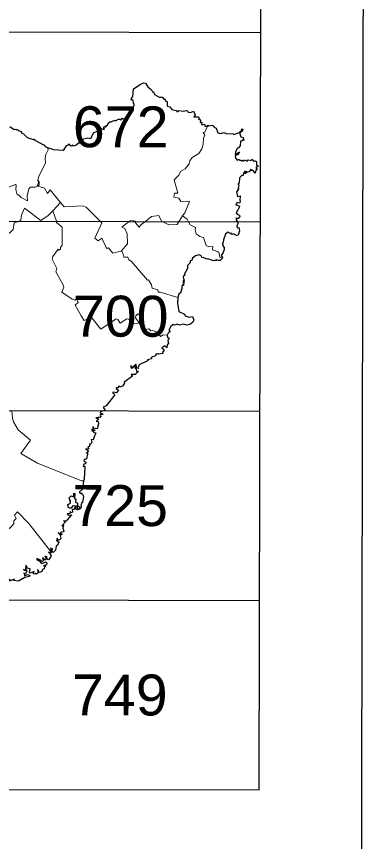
# Model space of a CAD drawing. Extents: x 483840 to 488445, y 4386047 to 4389027.
# Drawn here: x 488278.3 to 488445.3, y 4387758.2 to 4388151.7 of the extents above; entities that cross this region are included whole.
import ezdxf
from ezdxf.enums import TextEntityAlignment as Align

# ---------------------------------------------------------------- set-up
doc = ezdxf.new("R2010")
doc.units = 0
doc.header["$LTSCALE"] = 4
doc.header["$PDMODE"] = 32
doc.header["$PDSIZE"] = 2
doc.linetypes.add('DOTTED', pattern=[1.5, 0.3, -1.2])
for name, color, linetype, lineweight in [('1', 7, 'Continuous', 13), ('2', 7, 'DOTTED', 13), ('3', 7, 'Continuous', 25)]:
    doc.layers.add(name, color=color, linetype=linetype, lineweight=lineweight)

msp = doc.modelspace()

# ---------------------------------------------------------------- linework, layer by layer
at = {"layer": '1', "lineweight": 25}
for p, q in [((488394.11, 4387782.86), (488394.98, 4388234.5)), ((487979.13, 4388144.96), (488394.81, 4388144.16)), ((487840.39, 4388054.9), (488394.63, 4388053.84)), ((487840.22, 4387964.58), (488394.46, 4387963.51)), ((487840.04, 4387874.26), (488394.28, 4387873.19)), ((488116.99, 4387783.39), (488394.11, 4387782.86))]:
    msp.add_line(p, q, dxfattribs=at)
msp.add_lwpolyline([(483845.33, 4389027.42), (488445.32, 4389018.55), (488439.58, 4386047.03), (483839.59, 4386055.9), (483845.33, 4389027.2)], dxfattribs=at)
at = {"layer": '3'}
for p, q in [((488368.22, 4388099.37), (488368.93, 4388099.37)), ((488368.93, 4388099.37), (488369.72, 4388099.83)), ((488369.72, 4388099.83), (488369.49, 4388099.36))]:
    msp.add_line(p, q, dxfattribs=at)
at = {"layer": '3', "lineweight": 13}
msp.add_line((488357.52, 4388056.66), (488355.91, 4388054.17), dxfattribs=at)
at = {"layer": '3'}
for points in [[(488334.17, 4388110.24), (488333.96, 4388111.87), (488333.27, 4388112.11), (488333.16, 4388111.75), (488332.83, 4388112.48), (488333.21, 4388112.45), (488333.49, 4388113.42), (488333.9, 4388113.35), (488334.09, 4388117.22), (488337.38, 4388119.26)], [(488337.38, 4388119.26), (488338.99, 4388120.12), (488339.91, 4388120), (488341.05, 4388118.24), (488342.77, 4388116.73), (488343.16, 4388115.81), (488343.76, 4388115.76), (488344.23, 4388114.53), (488346.39, 4388113.19), (488348.04, 4388113.18), (488348.72, 4388112.21), (488349.26, 4388112.24), (488349.37, 4388111.38)], [(488325.28, 4388102.08), (488325.57, 4388101.94), (488326.98, 4388102.81), (488327.72, 4388102.7), (488328.05, 4388102.2), (488328.67, 4388103.25), (488329.29, 4388102.91), (488330.14, 4388103.11), (488330.76, 4388104.02), (488331.77, 4388104.33), (488332.44, 4388105.15), (488332.18, 4388106.83), (488333.65, 4388107.61), (488334.43, 4388109.33), (488334.53, 4388109.96), (488334.17, 4388110.24)], [(488349.37, 4388111.38), (488349.98, 4388111.38), (488350.26, 4388110.68), (488350.21, 4388108.88), (488351.45, 4388108.56), (488352.51, 4388107.39), (488354.53, 4388106.84), (488354.93, 4388106.32), (488355.74, 4388106.83), (488357.89, 4388106.49), (488359.49, 4388106.94), (488359.97, 4388106.8), (488360.19, 4388106.09), (488361.37, 4388105.94)], [(488361.37, 4388105.94), (488362.74, 4388106.5), (488363.5, 4388104.75), (488362.96, 4388103.81), (488364.94, 4388103.94), (488365.43, 4388103.27), (488365.17, 4388102.66), (488365.64, 4388102.73), (488366.13, 4388102.15), (488365.9, 4388101.17), (488366.69, 4388101.31), (488366.64, 4388100.21), (488366.95, 4388100.08), (488368.03, 4388100.34), (488368.22, 4388099.37)], [(488325.28, 4388102.08), (488323.89, 4388101.66), (488323.73, 4388101.27), (488322.84, 4388101.34), (488321.92, 4388100.57), (488321.36, 4388099.46), (488320.88, 4388099.67), (488320.89, 4388099.26)], [(488275.21, 4388099.24), (488277.18, 4388097.87), (488278.09, 4388098), (488278.38, 4388097.62), (488278.93, 4388097.9), (488279.2, 4388097.28), (488280.55, 4388096.91), (488280.95, 4388096.08), (488281.69, 4388095.83), (488283.39, 4388094.07), (488286.31, 4388093.05), (488286.88, 4388092.92), (488286.57, 4388093.23), (488286.84, 4388093.25), (488287.38, 4388092.63)], [(488320.89, 4388099.26), (488320.73, 4388098.77), (488320.3, 4388099.08), (488319.72, 4388098.76), (488320.17, 4388098.05), (488319.93, 4388097.74), (488318.83, 4388098.07), (488318, 4388097.25), (488317.09, 4388097.61), (488316.91, 4388097.1), (488314.94, 4388096.07), (488313.62, 4388093.35), (488312.4, 4388093.72)], [(488369.72, 4388099.83), (488370.03, 4388099.55), (488371.72, 4388099.93), (488372.47, 4388099.38)], [(488372.47, 4388099.38), (488372.59, 4388098.93), (488373.63, 4388098.54), (488374.45, 4388096.26), (488375.72, 4388095.84), (488377.44, 4388096.45), (488378.37, 4388095.93), (488381.75, 4388095.8), (488382.1, 4388095.37), (488384.52, 4388096.46), (488385.62, 4388097.28), (488385.88, 4388098.12), (488386.55, 4388097.81), (488385.99, 4388097.36), (488386.1, 4388097.07)], [(488312.4, 4388093.72), (488309.73, 4388093.11), (488309.99, 4388092.87), (488309.08, 4388091.33), (488307.89, 4388091.38), (488306.59, 4388090.25), (488305.48, 4388089.89), (488305.26, 4388090.4), (488304.21, 4388089.86), (488303.87, 4388090.37)], [(488386.1, 4388097.07), (488384.99, 4388096.46), (488384.9, 4388095.78), (488385.37, 4388094.27), (488386.55, 4388094.01), (488386.72, 4388092.55), (488386.08, 4388092.82), (488385.75, 4388092.19), (488385.27, 4388092.21), (488385.07, 4388090.09), (488384.29, 4388089.04), (488383.82, 4388088.97), (488382.78, 4388087.15), (488382.7, 4388085.96), (488383.32, 4388086.24)], [(488287.38, 4388092.63), (488291.15, 4388090.55), (488291.57, 4388090.63), (488291.88, 4388089.91), (488293.32, 4388089.13)], [(488303.87, 4388090.37), (488303.21, 4388090.89), (488302.99, 4388090.38), (488301.98, 4388090.1), (488300.66, 4388087.77), (488296.19, 4388088.18), (488293.32, 4388089.13)], [(488383.32, 4388086.24), (488384.65, 4388087.12), (488383.86, 4388085.9), (488382.73, 4388085.25), (488382.88, 4388084.13), (488383.54, 4388083.23), (488384.55, 4388083.63), (488384.67, 4388083.13), (488385.6, 4388083.25), (488385.74, 4388082.75), (488386.31, 4388083.16), (488386.72, 4388082.77), (488387.09, 4388083.36), (488388.43, 4388082.79), (488388.92, 4388083.28), (488390.35, 4388083.08), (488390.67, 4388083.71), (488391.58, 4388082.95), (488391.49, 4388082.52), (488392.29, 4388082.95)], [(488392.29, 4388082.95), (488392.77, 4388082.58), (488392.9, 4388080.82), (488393.71, 4388080.57), (488393.39, 4388079.82), (488392.69, 4388079.96), (488392.69, 4388079.41), (488393.28, 4388078.87), (488392.46, 4388078.41), (488392.16, 4388077.01), (488391.29, 4388078.3), (488390.64, 4388078.31), (488390.11, 4388078.85), (488389.3, 4388077.62), (488388.41, 4388077.55), (488387.31, 4388076.75), (488387.48, 4388077.32)], [(488387.48, 4388077.32), (488388.2, 4388077.58), (488387.34, 4388077.96), (488387.3, 4388077.4), (488386.63, 4388077.23), (488386.51, 4388075.95), (488385.85, 4388075.91), (488384.66, 4388074.76), (488384.56, 4388072.18), (488383.95, 4388071.95), (488384.48, 4388071.22), (488384.06, 4388070.04), (488384.36, 4388069.58), (488383.93, 4388069.58), (488384.05, 4388068.97), (488383.29, 4388068.12)], [(488383.29, 4388068.12), (488383.85, 4388065.89), (488385.04, 4388066.19), (488384.86, 4388064), (488385.23, 4388063.58), (488384.7, 4388062.75), (488383.46, 4388063), (488383.25, 4388062.2), (488382.79, 4388062.02), (488384.67, 4388061.24), (488384.54, 4388060.68)], [(488384.54, 4388060.68), (488383.07, 4388058.06), (488383.55, 4388057.77), (488383.45, 4388057.45), (488384.67, 4388057.02), (488384.96, 4388056.3), (488384.15, 4388055.4), (488382.9, 4388055.4), (488383.24, 4388055.16), (488383.15, 4388054.39), (488383.61, 4388054.24)], [(488383.61, 4388054.24), (488383.91, 4388054.01), (488383.88, 4388052.95), (488383.38, 4388051.69), (488383.67, 4388050.91), (488384.45, 4388051.01), (488384.67, 4388049.53), (488384.17, 4388047.43), (488383.35, 4388047.23), (488381.65, 4388048.1), (488381.08, 4388047.73), (488380.6, 4388048.49), (488380.28, 4388048.24), (488379.23, 4388048.88), (488378.07, 4388047.89), (488377.13, 4388045.19)], [(488377.13, 4388045.19), (488376.98, 4388043.93), (488376.49, 4388043.52), (488376.94, 4388042.77), (488376.61, 4388042.48), (488377.37, 4388041.6), (488377.37, 4388040.62), (488376.97, 4388039.16), (488375.95, 4388037.68), (488376.54, 4388036.7), (488376.38, 4388036.35)], [(488363.69, 4388037.58), (488362.36, 4388036.42), (488362.04, 4388035.39), (488361.2, 4388035.26), (488361.16, 4388034.17), (488359.98, 4388033), (488359.86, 4388031.5), (488358.33, 4388028.74), (488358.86, 4388028.32), (488358.06, 4388028.09), (488357.91, 4388027.32), (488358.4, 4388025.66), (488358.08, 4388025.83), (488357.76, 4388025.12), (488358.54, 4388025.37), (488358.18, 4388024.94), (488358.36, 4388024.66), (488357.9, 4388024.5), (488358.23, 4388023.97), (488357.51, 4388023.88)], [(488376.38, 4388036.35), (488375.48, 4388035.41), (488374.68, 4388035.28), (488373.83, 4388035.7), (488373.64, 4388035.21), (488373.31, 4388035.45), (488372.28, 4388035.15), (488369.69, 4388036.15), (488369.11, 4388035.94), (488367.34, 4388036.79), (488366.89, 4388036.6), (488366.46, 4388037.65), (488365.5, 4388038.07), (488363.69, 4388037.58)], [(488357.51, 4388023.88), (488358.12, 4388023.57), (488357.14, 4388023.3), (488357.21, 4388021.85), (488356.77, 4388021.11), (488357.01, 4388020.94), (488356.41, 4388019.76), (488355.71, 4388019.28), (488355.37, 4388017.63)], [(488355.37, 4388017.63), (488355.08, 4388015), (488355.79, 4388011.04), (488358.51, 4388009.75), (488358.76, 4388009.01)], [(488358.76, 4388009.01), (488360.64, 4388008.31), (488362.36, 4388008.58), (488362.92, 4388006.94), (488362.42, 4388005.91), (488361.3, 4388005.04), (488359.65, 4388004.5), (488357.99, 4388005.04), (488356.07, 4388004.58), (488354.94, 4388004.97), (488354.04, 4388004.43)], [(488354.04, 4388004.43), (488353.08, 4388004.75), (488351.98, 4388003.94), (488351.06, 4388002.14), (488351.71, 4388001.32), (488350.89, 4388001.01), (488350.25, 4387999.71)], [(488350.25, 4387999.71), (488350.33, 4387998.6), (488351.24, 4387998.28), (488350.56, 4387997.26), (488350.87, 4387995.59), (488350.25, 4387995.07), (488350.01, 4387993.73), (488349.18, 4387994.61), (488347.65, 4387993.75), (488348.66, 4387992.82), (488348.57, 4387992.14), (488347.96, 4387991.71), (488348.19, 4387990.94), (488346.15, 4387990.6), (488345.75, 4387990.95), (488345.42, 4387990.66), (488344.97, 4387990.85), (488344.61, 4387989.94), (488342.6, 4387989.09), (488342.74, 4387988.42), (488340.87, 4387987.89), (488340.82, 4387987.6), (488341.2, 4387987.61)], [(488341.2, 4387987.61), (488336.87, 4387985.58), (488336.32, 4387984.36), (488336.59, 4387983.86), (488335.72, 4387984.09), (488335.29, 4387985.93), (488333.45, 4387984.27), (488333.06, 4387984.34), (488333.04, 4387985.25), (488332.87, 4387984.26), (488333.3, 4387983.96), (488335.13, 4387985.2), (488334.77, 4387984.27), (488335.53, 4387983.26), (488335.61, 4387982.43), (488336.51, 4387982.63), (488334.89, 4387980.91), (488333.08, 4387981)], [(488333.08, 4387981), (488333.74, 4387980.23), (488329.75, 4387977.38), (488329.82, 4387976.9), (488328.89, 4387975.42), (488327.69, 4387974.92), (488327.16, 4387975.51), (488326.8, 4387974.63), (488325.9, 4387974.67), (488325.83, 4387974.34), (488326.94, 4387973.51), (488326.11, 4387972.27), (488325.47, 4387972.45)], [(488325.47, 4387972.45), (488324.34, 4387972.49), (488324.27, 4387972.05), (488324.92, 4387971.82), (488325.05, 4387971.11), (488321.04, 4387966.04), (488319.74, 4387965.42), (488320.56, 4387963.77)], [(488320.56, 4387963.77), (488318.24, 4387963.2), (488318.52, 4387962.35), (488319.62, 4387962.2), (488319.01, 4387961.72), (488318.38, 4387962.01), (488318.18, 4387961.53), (488318.57, 4387960.79), (488318.28, 4387960.45), (488317.33, 4387960.65), (488317.55, 4387960.23), (488316.21, 4387960.36), (488317.42, 4387959.67), (488316.72, 4387958.82)], [(488316.72, 4387958.82), (488316.35, 4387958.68), (488317.28, 4387958.55), (488317.47, 4387957.52), (488316.9, 4387955.06), (488315.24, 4387955.44), (488314.73, 4387956.1), (488314.87, 4387955.09), (488314.15, 4387954.76), (488315.19, 4387954.77), (488315.82, 4387954.26), (488314.22, 4387953.95), (488314.85, 4387954.03), (488315.31, 4387953.25), (488316.12, 4387953.18), (488315.47, 4387951.21)], [(488315.47, 4387951.21), (488314.89, 4387949.79), (488313.93, 4387949.94), (488314.29, 4387948.7), (488313.78, 4387947.71), (488313.1, 4387947.67), (488313.22, 4387946.61), (488312.43, 4387946.52), (488312.84, 4387945.54), (488311.31, 4387945.35), (488312.41, 4387944.83), (488312.58, 4387944.33), (488311.67, 4387943.53), (488312.19, 4387943.58), (488312.24, 4387943.03), (488311.72, 4387940.76), (488311.19, 4387940.47)], [(488311.19, 4387940.47), (488310.82, 4387940.56), (488310.42, 4387939.86), (488311.41, 4387939.22), (488311.31, 4387938.41), (488310.54, 4387938.25), (488310.15, 4387937.46), (488310.38, 4387937.02), (488310.82, 4387937.38), (488310.88, 4387936.99), (488310.58, 4387931.01), (488310.26, 4387930.2)], [(488310.26, 4387930.2), (488309.83, 4387926.23), (488308.43, 4387925.01), (488308.37, 4387924.53), (488309.01, 4387924.23), (488309.35, 4387924.51), (488309.28, 4387924.05), (488309.81, 4387923.82), (488310.24, 4387922.91), (488309.78, 4387919.96), (488309.25, 4387919.57), (488309.44, 4387919.16)], [(488302.83, 4387918.59), (488302.88, 4387919.04), (488304.03, 4387919.53), (488303.94, 4387920.6), (488304.32, 4387920.7), (488303.97, 4387920.79), (488303.54, 4387922.1), (488304.44, 4387923.16), (488305.4, 4387922.63), (488305.73, 4387923.06), (488305.72, 4387924.32), (488306.11, 4387924.14), (488306.01, 4387922.04), (488306.62, 4387921.49), (488306.42, 4387920.37), (488306.59, 4387919.91), (488307.5, 4387919.76), (488307.47, 4387918.59)], [(488302.83, 4387918.59), (488302.81, 4387917.71), (488303.57, 4387917.4), (488304.6, 4387917.39), (488305.61, 4387918.44), (488306.34, 4387918.29), (488306.59, 4387917.85), (488305.65, 4387916.57), (488304.95, 4387916.61), (488305.12, 4387915.27), (488304.47, 4387915), (488303.9, 4387915.58), (488303.92, 4387914.84), (488303.54, 4387914.48), (488302.59, 4387914.56), (488302.56, 4387914.19), (488303.29, 4387913.84), (488304.55, 4387914.11), (488302.56, 4387911.68)], [(488307.47, 4387918.59), (488307.36, 4387916.88), (488307.7, 4387916.6), (488308.93, 4387917.1), (488309.34, 4387917.82), (488309.22, 4387918.6)], [(488309.44, 4387919.16), (488309.14, 4387919.07), (488309.22, 4387918.6)], [(488302.56, 4387911.68), (488302.25, 4387911.04), (488300.71, 4387911.11), (488301.69, 4387910.75), (488300.01, 4387908.82), (488300.8, 4387909.2), (488300.38, 4387907.69), (488300.92, 4387906.35), (488300.57, 4387905.92), (488299.49, 4387905.72), (488299.54, 4387905.31), (488299.04, 4387905.11), (488298.29, 4387905.44), (488299.06, 4387904.59), (488299.98, 4387905.14), (488300.12, 4387904.87), (488299.19, 4387904.17), (488299.45, 4387902.99), (488299.2, 4387902.28), (488298.09, 4387901.78), (488298.03, 4387902.04)], [(488298.03, 4387902.04), (488297.72, 4387902.88), (488297.72, 4387902.03), (488297.32, 4387901.86), (488297.78, 4387901.71), (488298.03, 4387900.97), (488298.33, 4387901.33), (488298.55, 4387901.02), (488298.06, 4387899.68), (488297.34, 4387899.02), (488296.88, 4387897.14), (488295.78, 4387896.08), (488295.37, 4387896.59), (488295.58, 4387898.02), (488295.19, 4387897.44), (488294.78, 4387898.21), (488294.5, 4387898.09), (488294.85, 4387897.08), (488294.61, 4387896.67)], [(488289.67, 4387892.5), (488288.02, 4387893.19), (488288.03, 4387892.42), (488288.3, 4387892.75), (488288.19, 4387892.27), (488288.66, 4387892.67), (488288.48, 4387892.33), (488288.8, 4387892.6), (488288.8, 4387892.19), (488289.01, 4387892.5), (488288.84, 4387892.18), (488289.53, 4387892.19), (488289.35, 4387891.91), (488290.22, 4387890.84), (488292.51, 4387891.59), (488292.78, 4387890.8), (488292.6, 4387890.26), (488291.26, 4387889.74), (488292.3, 4387889.61), (488291.65, 4387889.06), (488291.57, 4387888.26), (488290.72, 4387887.93), (488290.45, 4387886.96), (488289.37, 4387886.56), (488288.84, 4387887.11)], [(488294.61, 4387896.67), (488294.83, 4387895.74), (488293.66, 4387896.23), (488295.04, 4387894.7), (488294.59, 4387894.59), (488294.77, 4387894.05), (488293.68, 4387892.65), (488293.03, 4387892.97), (488292.76, 4387894.11), (488292.37, 4387893.89), (488291.78, 4387894.55), (488292.44, 4387893.18), (488292.2, 4387892.4), (488290.69, 4387893.52), (488291.29, 4387892.06), (488290.36, 4387891.8), (488289.67, 4387892.5)], [(488288.84, 4387887.11), (488288.91, 4387887.55), (488288.3, 4387888.02), (488288.7, 4387886.43), (488287.9, 4387885.71), (488287.38, 4387886.1), (488286.73, 4387885.75), (488286.3, 4387886.04), (488286.7, 4387887.03), (488284.87, 4387886.2), (488284.57, 4387886.66), (488284.91, 4387888.3), (488283.45, 4387888.61), (488283.16, 4387889.7), (488282.77, 4387889.89), (488282.71, 4387888.29), (488283.19, 4387888.34), (488282.28, 4387887.64), (488281.7, 4387888), (488281.98, 4387887.63)], [(488281.98, 4387887.63), (488282.82, 4387887.72), (488283.26, 4387887.35), (488282.7, 4387885.95), (488281.85, 4387886.25), (488282.3, 4387885.48), (488282.08, 4387884.99), (488283.58, 4387885.56), (488284.68, 4387885.12), (488284.52, 4387884.65), (488282.3, 4387884.09), (488279.3, 4387882.35), (488276.92, 4387882.68), (488277.34, 4387883.33), (488275.36, 4387882.64), (488275.04, 4387882.64), (488275.19, 4387883.3), (488275, 4387883.08)]]:
    msp.add_lwpolyline(points, dxfattribs=at)
at = {"layer": '3', "lineweight": 13}
for points in [[(488369.49, 4388099.36), (488368.25, 4388096.49), (488367.34, 4388096.35), (488368.11, 4388095.14), (488367.51, 4388093.76), (488367.37, 4388090.76), (488366.72, 4388088.57), (488365.33, 4388086.34), (488362.09, 4388084.49), (488361.08, 4388082.91), (488360.77, 4388081.46), (488358.84, 4388079.14), (488356.61, 4388077.79), (488355.76, 4388076.03), (488353.52, 4388073.85), (488355.36, 4388067.45), (488353.74, 4388067.39), (488353.32, 4388065.57), (488355.74, 4388065.04), (488356.8, 4388063.45), (488359.72, 4388063.6)], [(488293.32, 4388089.13), (488293.49, 4388088.06), (488292.4, 4388085.92), (488292.06, 4388084.19), (488292.11, 4388081.86), (488288.97, 4388075.33), (488288.55, 4388073.59)], [(488288.55, 4388073.59), (488288.77, 4388072.53), (488288.24, 4388070.83), (488287.22, 4388070.33), (488284.97, 4388070.3), (488284.24, 4388069.6), (488283.36, 4388066.16), (488283.52, 4388063.73), (488280.6, 4388065.33), (488279.34, 4388066.69), (488278.69, 4388066.6), (488278.04, 4388069.18), (488278.13, 4388071.25), (488277.8, 4388071.55), (488272.59, 4388069.5), (488268.84, 4388069.02), (488267.93, 4388067.01), (488266.45, 4388065.68), (488263.99, 4388066.32)], [(488288.55, 4388073.59), (488289.22, 4388072.79), (488289.08, 4388071.36), (488288.51, 4388070.83), (488291.63, 4388069.91), (488293.08, 4388067.34), (488294.42, 4388069.09), (488299.39, 4388063.03)], [(488299.39, 4388063.03), (488295.66, 4388059.07), (488297.47, 4388054.08)], [(488299.39, 4388063.03), (488301.09, 4388060.99), (488309.78, 4388061.4), (488311.61, 4388060.72), (488318.22, 4388054.09)], [(488359.72, 4388063.6), (488360.82, 4388063.55), (488358.67, 4388058.12), (488357.52, 4388056.66)], [(488295.66, 4388059.07), (488293.51, 4388056.83), (488289.96, 4388054.42), (488282.12, 4388060.26), (488280.76, 4388056.99), (488280.34, 4388054.58), (488279.74, 4388054.07)], [(488297.47, 4388054.08), (488297.49, 4388053.52), (488300.12, 4388051.27), (488300.16, 4388042.65), (488299.39, 4388041.57), (488299.3, 4388040.69), (488298.67, 4388040.3), (488298.14, 4388040.75), (488295.75, 4388037.24), (488295.34, 4388035.95), (488297.59, 4388031.46), (488297.16, 4388029.87), (488300.49, 4388024.13), (488300.86, 4388022.61), (488299.9, 4388020.26), (488304.84, 4388016.83), (488306.34, 4388016.4), (488306.9, 4388017.05), (488307.79, 4388015.27), (488306.33, 4388014.11), (488309.25, 4388008.92)], [(488318.22, 4388054.09), (488319.07, 4388053.29), (488315.66, 4388045.99), (488317.23, 4388044.7), (488318.97, 4388045.96), (488321.11, 4388041.51), (488321.61, 4388041.1), (488322.15, 4388041.36), (488324.37, 4388038.88), (488325.37, 4388039.1)], [(488332.25, 4388054.11), (488328.62, 4388051.26), (488330.03, 4388050.6), (488331.2, 4388048.13), (488331.37, 4388043.31), (488328.26, 4388039.8), (488325.37, 4388039.1)], [(488332.25, 4388054.11), (488332.81, 4388054.41), (488335.1, 4388054.12)], [(488335.1, 4388054.12), (488335.06, 4388053.3), (488336.88, 4388051.29), (488337.72, 4388052.38), (488340.09, 4388054.13)], [(488340.09, 4388054.13), (488342.69, 4388056.29), (488346.19, 4388056.87), (488347.47, 4388054.15)], [(488347.47, 4388054.15), (488350.97, 4388052.32), (488354.92, 4388052.56), (488355.91, 4388054.17)], [(488357.52, 4388056.66), (488359.77, 4388055), (488360.2, 4388054.18)], [(488360.2, 4388054.18), (488361.24, 4388052.42), (488363.67, 4388051.11), (488363.5, 4388049.94), (488364.01, 4388048.05), (488365.74, 4388046.79), (488367.54, 4388046.35), (488368.87, 4388042.48), (488370.05, 4388041.9), (488371.99, 4388042.03), (488371.77, 4388040.5), (488374.82, 4388039.3), (488375.39, 4388036.96), (488376.38, 4388036.35)], [(488279.74, 4388054.07), (488277.15, 4388053.33), (488276.81, 4388050.18), (488273.51, 4388047.1), (488272.95, 4388045.22), (488269.67, 4388046.65), (488263.99, 4388038.38), (488260.4, 4388032.18), (488261.46, 4388031.23), (488261.06, 4388030.69), (488261.7, 4388029.79), (488260.78, 4388027.72), (488262.93, 4388026.65), (488261.59, 4388018.33), (488261.98, 4388017.63), (488260.94, 4388015.99), (488258.99, 4388015.69), (488256.96, 4388014.65), (488256.92, 4388013.5), (488257.42, 4388012.07), (488258.95, 4388011.64), (488260.25, 4388010.69), (488261.06, 4388009.51), (488260.9, 4388008.89)], [(488328.26, 4388039.8), (488328.92, 4388039.46), (488329.48, 4388036.95), (488331.46, 4388036.91), (488331.89, 4388035.59), (488333.18, 4388034.86), (488340.76, 4388025.89), (488341.27, 4388026.08), (488342.69, 4388023.66), (488343.1, 4388022.18), (488345.74, 4388021.35), (488345.94, 4388020.24), (488346.94, 4388020.32), (488355.37, 4388017.63)], [(488309.25, 4388008.92), (488310.55, 4388006.68), (488313.18, 4388007.83), (488313.58, 4388008.77), (488318.6, 4388002.63), (488325.42, 4388007.16)], [(488335.28, 4388008.96), (488335.09, 4388008.07), (488336.52, 4388006.09), (488336.32, 4388005.4), (488334.03, 4388005.08), (488332.27, 4388007.19), (488330.94, 4388007.6), (488327.74, 4388005.41), (488326.65, 4388007.27), (488325.84, 4388007.46), (488325.42, 4388007.16)], [(488335.28, 4388008.96), (488336.16, 4388009.89), (488337.43, 4388008.97)], [(488337.43, 4388008.97), (488338.45, 4388006.68), (488336.93, 4388005.68), (488337.1, 4388004.76), (488337.67, 4388004.28), (488339.11, 4388005.08), (488339.45, 4388002.44), (488341.41, 4388002.7), (488342.38, 4388001.79), (488343.33, 4388001.91), (488345.91, 4388000.8), (488347.11, 4387999.06), (488348.33, 4387999.9), (488350.25, 4387999.71)], [(488275.3, 4387963.75), (488275.62, 4387963.45), (488276.16, 4387963.61), (488276.39, 4387960.16), (488276.97, 4387958.36), (488279.07, 4387954.56), (488285, 4387949.72), (488280.48, 4387943.33), (488288.28, 4387938.72), (488309.3, 4387930.19), (488310.26, 4387930.2)], [(488256.02, 4387907.66), (488258.66, 4387907.96), (488260.11, 4387908.8), (488262.88, 4387909.32), (488264.79, 4387915.36), (488274.94, 4387907.55), (488277.06, 4387909.82), (488277.1, 4387911.11), (488278.11, 4387912.22), (488277.4, 4387913.82), (488278.86, 4387915.4), (488284.22, 4387909.87), (488294.61, 4387896.67)]]:
    msp.add_lwpolyline(points, dxfattribs=at)
at = {"layer": '3'}
msp.add_point((488307.28, 4387917.47), dxfattribs=at)

# ---------------------------------------------------------------- texts
at = {"layer": '2', "width": 1.05}
for s, p in [('672', (488328.05, 4388089.36)), ('700', (488328.01, 4387999.04)), ('725', (488327.77, 4387908.71)), ('749', (488327.6, 4387818.39))]:
    msp.add_text(s, height=19.5, rotation=359.889, dxfattribs=at).set_placement(p, align=Align.CENTER)

doc.saveas('drawing.dxf')
